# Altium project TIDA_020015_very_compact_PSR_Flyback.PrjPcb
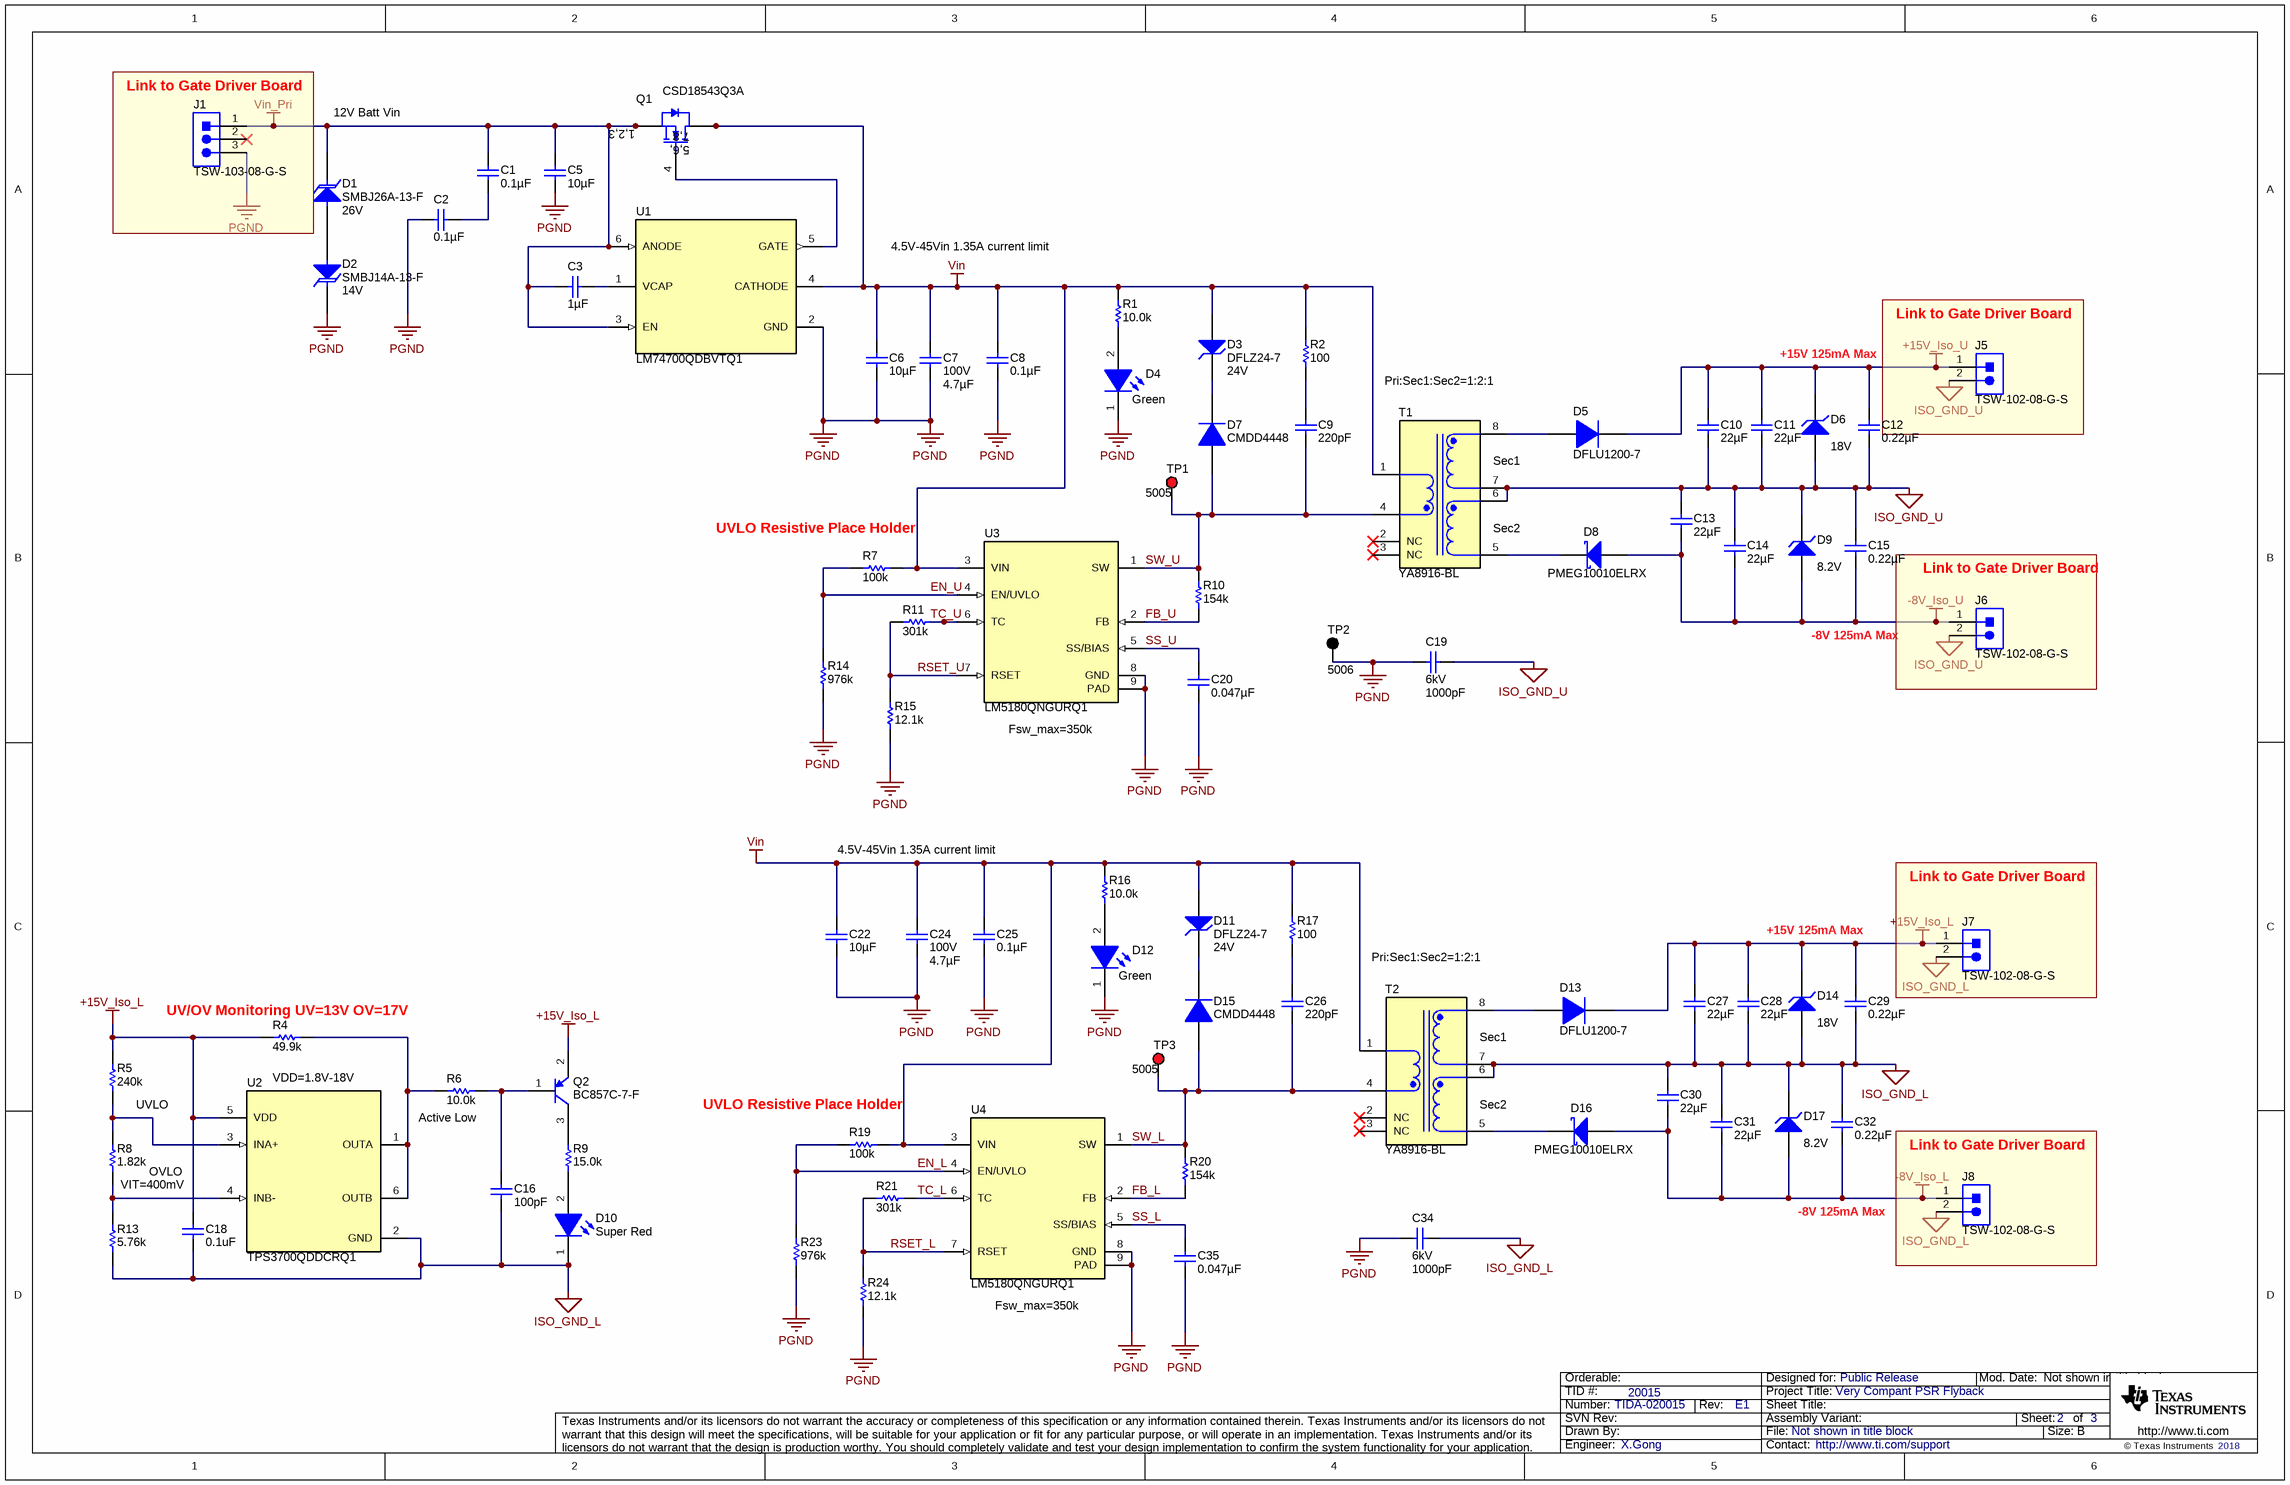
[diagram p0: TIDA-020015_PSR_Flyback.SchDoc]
CopyrightYear: 2018; PCB_Layout: X.Gong; PCB_Rev: E1; PRJ_Customer: Public Release; PRJ_Engineer: X.Gong; PRJ_Number: TIDA-020015; PRJ_Title: Very Compant PSR Flyback; SCH_Rev: E1; TechSupport: http://www.ti.com/support; TID: 20015
2 sheets, 91 parts. Net scope: global (net labels, ports and power ports of the same name join across sheets).
Board file: TIDA_020015_PCB.PcbDoc
Sheets:
  TIDA-020015_PSR_Flyback.SchDoc
  TIDA_020015_PSR_Flyback_Hardware.SchDoc

## Sheet TIDA-020015_PSR_Flyback.SchDoc
size 431 x 279 mm; Date: Not shown in title block; ApprovedBy: Not shown in title block; CheckedBy: Not shown in title block; Author: Not shown in title block; CompanyName: Not shown in title block; Engineer: Not shown in title block; Organization: Not shown in title block; Address1: Not shown in title block; Address2: Not shown in title block; Address3: Not shown in title block; Address4: Not shown in title block; DocumentNumber: 1; Revision: Use project parameter SCH_Rev; SheetNumber: 2; SheetTotal: 3; PageSetup: Record=PageOptions¦CenterHorizontal=True¦CenterVertical=True¦PrintScale=1.00¦XCorrection=1.00¦YCorrection=1.00¦PrintKind=0¦BorderSize=5000000¦LeftOffset=0¦BottomOffset=0¦Orientation=2¦PaperLength=1000¦PaperWidth=1000¦Scale=100¦PaperSource=15¦PrintQuality=600¦MediaType=1¦DitherType=10¦PaperKind=Letter¦PrintScaleMode=1

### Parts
C1  ValueDisplayed: 0.1µF  [0805_HV]  (hidden comment: GRM21BR71H104KA01L)
C2  ValueDisplayed: 0.1µF  [0805_HV]  (hidden comment: GRM21BR71H104KA01L)
C3  ValueDisplayed: 1µF  [0603]  (hidden comment: GRM188R61H105KAALD)
C5  ValueDisplayed: 10µF  [2220_250]  (hidden comment: C5750X7S2A106K230KB)
C6  ValueDisplayed: 10µF  [2220_250]  (hidden comment: C5750X7S2A106K230KB)
C7  VDC_V: 100V  ValueDisplayed: 4.7µF  [1210_220]  (hidden comment: GCM32DC72A475KE02L)
C8  ValueDisplayed: 0.1µF  [0805_HV]  (hidden comment: GRM21BR72A104KAC4L)
C9  ValueDisplayed: 220pF  [0603]  (hidden comment: GRM1885C2A221JA01D)
C10  ValueDisplayed: 22µF  [0805_HV]  (hidden comment: GRM21BR61E226ME44L)
C11  ValueDisplayed: 22µF  [0805_HV]  (hidden comment: GRM21BR61E226ME44L)
C12  ValueDisplayed: 0.22µF  [0805_HV]  (hidden comment: GRM21BR71H224KA01L)
C13  ValueDisplayed: 22µF  [0805_HV]  (hidden comment: GRM21BR61E226ME44L)
C14  ValueDisplayed: 22µF  [0805_HV]  (hidden comment: GRM21BR61E226ME44L)
C15  ValueDisplayed: 0.22µF  [0805_HV]  (hidden comment: GRM21BR71H224KA01L)
C16  ValueDisplayed: 100pF  [0603]  (hidden comment: GRM1885C2A101JA01D)
C18  ValueDisplayed: 0.1uF  [0402]  (hidden comment: Capacitor)
C19  VDC_V: 6kV  ValueDisplayed: 1000pF  [S102_1500x800x1800]  (hidden comment: S102M59Z5UU83L0R)
C20  ValueDisplayed: 0.047µF  [0603]  (hidden comment: GRM188R71C473KA01D)
C22  ValueDisplayed: 10µF  [2220_250]  (hidden comment: C5750X7S2A106K230KB)
C24  VDC_V: 100V  ValueDisplayed: 4.7µF  [1210_220]  (hidden comment: GCM32DC72A475KE02L)
C25  ValueDisplayed: 0.1µF  [0805_HV]  (hidden comment: GRM21BR72A104KAC4L)
C26  ValueDisplayed: 220pF  [0603]  (hidden comment: GRM1885C2A221JA01D)
C27  ValueDisplayed: 22µF  [0805_HV]  (hidden comment: GRM21BR61E226ME44L)
C28  ValueDisplayed: 22µF  [0805_HV]  (hidden comment: GRM21BR61E226ME44L)
C29  ValueDisplayed: 0.22µF  [0805_HV]  (hidden comment: GRM21BR71H224KA01L)
C30  ValueDisplayed: 22µF  [0805_HV]  (hidden comment: GRM21BR61E226ME44L)
C31  ValueDisplayed: 22µF  [0805_HV]  (hidden comment: GRM21BR61E226ME44L)
C32  ValueDisplayed: 0.22µF  [0805_HV]  (hidden comment: GRM21BR71H224KA01L)
C34  VDC_V: 6kV  ValueDisplayed: 1000pF  [S102_1500x800x1800]  (hidden comment: S102M59Z5UU83L0R)
C35  ValueDisplayed: 0.047µF  [0603]  (hidden comment: GRM188R71C473KA01D)
D1  SMBJ26A-13-F  value 26V  [SMB]
D2  SMBJ14A-13-F  value 14V  [SMB]
D3  DFLZ24-7  value 24V  [PowerDI123]
D4  value Green  [WL-SMCW_GREEN]  (hidden comment: 150060GS75000)
D5  DFLU1200-7  [PowerDI123]
D6  value 18V  [SOD-123]  (hidden comment: BZT52C18-7-F)
D7  CMDD4448  [SOD-323]
D8  PMEG10010ELRX  [SOD-123W]
D9  value 8.2V  [SOD-123]  (hidden comment: BZT52C8V2-7-F)
D10  value Super Red  [WL-SMCW_RED]  (hidden comment: 150060SS75000)
D11  DFLZ24-7  value 24V  [PowerDI123]
D12  value Green  [WL-SMCW_GREEN]  (hidden comment: 150060GS75000)
D13  DFLU1200-7  [PowerDI123]
D14  value 18V  [SOD-123]  (hidden comment: BZT52C18-7-F)
D15  CMDD4448  [SOD-323]
D16  PMEG10010ELRX  [SOD-123W]
D17  value 8.2V  [SOD-123]  (hidden comment: BZT52C8V2-7-F)
J1  TSW-103-08-G-S  [Samtec_TSW-103-08-x-S]
J5  TSW-102-08-G-S  [Samtec_TSW-102-08-x-S]
J6  TSW-102-08-G-S  [Samtec_TSW-102-08-x-S]
J7  TSW-102-08-G-S  [Samtec_TSW-102-08-x-S]
J8  TSW-102-08-G-S  [Samtec_TSW-102-08-x-S]
Q1  CSD18543Q3A  [DNH0008A]
Q2  BC857C-7-F  [SOT-23]
R1  ValueDisplayed: 10.0k  [0603]  (hidden comment: CRCW060310K0FKEA)
R2  ValueDisplayed: 100  [0805_HV]  (hidden comment: CRCW0805100RFKEA)
R4  ValueDisplayed: 49.9k  [0402]  (hidden comment: CRCW040249K9FKED)
R5  ValueDisplayed: 240k  [0402]  (hidden comment: CRCW0402240KFKED)
R6  ValueDisplayed: 10.0k  [0402]  (hidden comment: CRCW040210K0FKED)
R7  ValueDisplayed: 100k  [0805_HV]  (hidden comment: CRCW0805100KFKEA)
R8  ValueDisplayed: 1.82k  [0402]  (hidden comment: CRCW04021K82FKED)
R9  ValueDisplayed: 15.0k  [0603]  (hidden comment: CRCW060315K0FKEA)
R10  ValueDisplayed: 154k  [0603]  (hidden comment: CRCW0603154KFKEA)
R11  ValueDisplayed: 301k  [0603]  (hidden comment: CRCW0603301KFKEA)
R13  ValueDisplayed: 5.76k  [0402]  (hidden comment: CRCW04025K76FKED)
R14  ValueDisplayed: 976k  [0603]  (hidden comment: CRCW0603976KFKEA)
R15  ValueDisplayed: 12.1k  [0805_HV]  (hidden comment: CRCW080512K1FKEA)
R16  ValueDisplayed: 10.0k  [0603]  (hidden comment: CRCW060310K0FKEA)
R17  ValueDisplayed: 100  [0805_HV]  (hidden comment: CRCW0805100RFKEA)
R19  ValueDisplayed: 100k  [0805_HV]  (hidden comment: CRCW0805100KFKEA)
R20  ValueDisplayed: 154k  [0603]  (hidden comment: CRCW0603154KFKEA)
R21  ValueDisplayed: 301k  [0603]  (hidden comment: CRCW0603301KFKEA)
R23  ValueDisplayed: 976k  [0603]  (hidden comment: CRCW0603976KFKEA)
R24  ValueDisplayed: 12.1k  [0805_HV]  (hidden comment: CRCW080512K1FKEA)
T1  YA8916-BL  [Coilcraft_YA8916-BL]
T2  YA8916-BL  [Coilcraft_YA8916-BL]
TP1  5005  [Keystone5005]
TP2  5006  [Keystone5006]
TP3  5005  [Keystone5005]
U1  LM74700QDBVTQ1  [DBV0006A_N]
U2  TPS3700QDDCRQ1  [DDC0006A_N]
U3  LM5180QNGURQ1  [NGU0008C]
U4  LM5180QNGURQ1  [NGU0008C]

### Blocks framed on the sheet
Link to Gate Driver Board: J1
Link to Gate Driver Board: J5
Link to Gate Driver Board: J6
Link to Gate Driver Board: J7
Link to Gate Driver Board: J8

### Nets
+15V_Iso_L: C18.1 C27.1 C28.1 C29.1 D13.1(K) D14.1(K) J7.1 Q2.2(E) R4.1 R5.2 U2.5(VDD)
+15V_Iso_U: C10.1 C11.1 C12.1 D5.1(K) D6.1(K) J5.1
-8V_Iso_L: C30.2 C31.2 C32.2 D16.2(A) D17.2(A) J8.1
-8V_Iso_U: C13.2 C14.2 C15.2 D8.2(A) D9.2(A) J6.1
ISO_GND_L: C16.2 C18.2 C27.2 C28.2 C29.2 C30.1 C31.1 C32.1 C34.1 D10.1(K) D14.2(A) D17.1(K) J7.2 J8.2 R13.1 T2.6 T2.7 U2.2(GND)
ISO_GND_U: C10.2 C11.2 C12.2 C13.1 C14.1 C15.1 C19.1 D6.2(A) D9.1(K) J5.2 J6.2 T1.6 T1.7
PGND: C2.1 C5.2 C6.2 C7.2 C8.2 C19.2 C20.2 C22.2 C24.2 C25.2 C34.2 C35.2 D2.1(K) D4.1(K) D12.1(K) J1.3 R14.1 R15.1 R23.1 R24.1 TP2.1 U1.2(GND) U3.8(GND) U3.9(PAD) U4.8(GND) U4.9(PAD)
Vin: C6.1 C7.1 C8.1 C22.1 C24.1 C25.1 D3.2(A) D11.2(A) Q1.5(D) Q1.6(D) Q1.7(D) Q1.8(D) Q1.9(D) R1.2 R2.2 R7.2 R16.2 R17.2 R19.2 T1.1 T2.1 U1.4(CATHODE) U3.3(VIN) U4.3(VIN)
Vin_Pri: C1.1 C3.2 C5.1 D1.1(K) J1.1 Q1.1(S) Q1.2(S) Q1.3(S) U1.3(EN) U1.6(ANODE)
EN_L: R19.1 R23.2 U4.4(EN/UVLO)
EN_U: R7.1 R14.2 U3.4(EN/UVLO)
FB_L: R20.1 U4.2(FB)
FB_U: R10.1 U3.2(FB)
RSET_L: R21.2 R24.2 U4.7(RSET)
RSET_U: R11.2 R15.2 U3.7(RSET)
SS_L: C35.1 U4.5(SS/BIAS)
SS_U: C20.1 U3.5(SS/BIAS)
SW_L: C26.2 D15.2(A) R20.2 T2.4 TP3.1 U4.1(SW)
SW_U: C9.2 D7.2(A) R10.2 T1.4 TP1.1 U3.1(SW)
TC_L: R21.1 U4.6(TC)
TC_U: R11.1 U3.6(TC)
NetC1_2: C1.2 C2.2
NetC3_1: C3.1 U1.1(VCAP)
NetC9_1: C9.1 R2.1
NetC16_1: C16.1 Q2.1(B) R6.2
NetC26_1: C26.1 R17.1
NetD1_2: D1.2(A) D2.2(A)
NetD3_1: D3.1(K) D7.1(K)
NetD4_2: D4.2(A) R1.1
NetD5_2: D5.2(A) T1.8
NetD8_1: D8.1(K) T1.5
NetD10_2: D10.2(A) R9.1
NetD11_1: D11.1(K) D15.1(K)
NetD12_2: D12.2(A) R16.1
NetD13_2: D13.2(A) T2.8
NetD16_1: D16.1(K) T2.5
NetQ1_4: Q1.4(G) U1.5(GATE)
NetQ2_3: Q2.3(C) R9.2
NetR4_2: R4.2 R6.1 U2.1(OUTA) U2.6(OUTB)
NetR5_1: R5.1 R8.2 U2.3(INA+)
NetR8_1: R8.1 R13.2 U2.4(INB-)

Not connected (* = marked no-connect by the designer): J1 2*; T1 2(NC)* 3(NC)*; T2 2(NC)* 3(NC)*

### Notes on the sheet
- 12V Batt Vin
- 4.5V-45Vin 1.35A current limit
- +15V 125mA Max
- (near T1) Pri:Sec1:Sec2=1:2:1
- (near T1) Sec1
- (near R7) UVLO Resistive Place Holder
- (near T1) Sec2
- -8V 125mA Max
- (near U3) Fsw_max=350k
- (near T2) Pri:Sec1:Sec2=1:2:1
- (near R4) UV/OV Monitoring UV=13V OV=17V
- (near T2) Sec1
- UVLO
- VDD=1.8V-18V
- (near R19) UVLO Resistive Place Holder
- (near T2) Sec2
- OVLO
- (near R6) Active Low
- (near R8) VIT=400mV
- (near U4) Fsw_max=350k

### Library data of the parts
C1 C2 = GRM21BR71H104KA01L: CAP, CERM, 0.1 µF, 50 V,+/- 10%, X7R, 0805; Manufacturer: MuRata; Polarized: N; CompType: Capacitor; Value: 0.1uF; U/M: EA; Cap_F: 0.0000001; Tolerance_%: 10; VDC_V: 50; Value2: 50V; TaMin_C: -55; TaMax_C: 125; Cap_Case: 0805; SizeArea_mm2: 2.5; SizeAreaWB_mm2: 6.75; SizeX_mm: 2; SizeY_mm: 1.25; SizeZ_mm: 1.45; AEC Category: Q200; Green_Lifecycle: Active; Green_REACh: Passed
C3 = GRM188R61H105KAALD: CAP, CERM, 1 µF, 50 V,+/- 10%, X5R, 0603; Manufacturer: MuRata; Polarized: N; CompType: Capacitor; Value: 1uF; U/M: EA; Cap_F: 0.000001; Tolerance_%: 10; VDC_V: 50; Value2: 50V; TaMin_C: -55; TaMax_C: 85; SizeArea_mm2: 1.28; SizeAreaWB_mm2: 4.68; SizeX_mm: 1.6; SizeY_mm: 0.8; SizeZ_mm: 1; AEC Category: Q200; Green_Lifecycle: Active; Green_REACh: Passed
C5 C6 C22 = C5750X7S2A106K230KB: CAP, CERM, 10 µF, 100 V,+/- 10%, X7S, 2220; Manufacturer: TDK; Polarized: N; CompType: Capacitor; Value: 10uF; U/M: EA; Cap_F: 0.00001; Tolerance_%: 10; ESR_ohm: 0.003179; Value1: 0.003179 ohm; VDC_V: 100; Value2: 100V; IRMS_A: 5.11992; TaMin_C: -55; TaMax_C: 125; Cap_Case: 2220; SizeArea_mm2: 28.5; SizeAreaWB_mm2: 53.9; SizeX_mm: 5.7; SizeY_mm: 5; SizeZ_mm: 2.5; AEC Category: Q200
C7 C24 = CMP-0082268-1: CAP, CERM, 4.7 µF, 100 V,+/- 10%, X7S, AEC-Q200 Grade 1, 1210; Manufacturer: MuRata; TaMin_C: -55°C; ESR_ohm: 1m; Polarized: N; SizeAreaWB_mm2: 14.7; Value1: 0.001 ohm; U/M: EA; Value: 4.7uF; TaMax_C: 125°C; SizeZ_mm: 2.2; SizeX_mm: 3.2; SizeY_mm: 2.5; Cap_Case: 1210; SizeArea_mm2: 8; AEC Qualified: Y; IRMS_A: 6A; AEC Grade: 1; AEC Category: Q200
C8 C25 = GRM21BR72A104KAC4L: CAP, CERM, 0.1 µF, 100 V,+/- 10%, X7R, 0805; Manufacturer: MuRata; Polarized: N; CompType: Capacitor; Value: 0.1uF; U/M: EA; Cap_F: 0.0000001; Tolerance_%: 10; VDC_V: 100; Value2: 100V; TaMin_C: -55; TaMax_C: 125; Cap_Case: 0805; SizeArea_mm2: 2.5; SizeAreaWB_mm2: 6.75; SizeX_mm: 2; SizeY_mm: 1.25; SizeZ_mm: 1.45; AEC Category: Q200
C9 C26 = GRM1885C2A221JA01D: CAP, CERM, 220 pF, 100 V,+/- 5%, C0G/NP0, 0603; Manufacturer: MuRata; Polarized: N; CompType: Capacitor; Value: 220pF; U/M: EA; Cap_F: 0.00000000022; Tolerance_%: 5; VDC_V: 100; Value2: 100V; TaMin_C: -55; TaMax_C: 125; SizeArea_mm2: 1.28; SizeAreaWB_mm2: 4.68; SizeX_mm: 1.6; SizeY_mm: 0.8; SizeZ_mm: 1; AEC Category: Q200
C10 C11 C13 C14 C27 C28 C30 C31 = GRM21BR61E226ME44L: CAP, CERM, 22 µF, 25 V,+/- 20%, X5R, 0805; Manufacturer: MuRata; Polarized: N; CompType: Capacitor; Value: 22uF; U/M: EA; Cap_F: 0.000022; Tolerance_%: 20; VDC_V: 25; Value2: 25V; TaMin_C: -55; TaMax_C: 85; Cap_Case: 0805; SizeArea_mm2: 2.5; SizeAreaWB_mm2: 6.75; SizeX_mm: 2; SizeY_mm: 1.25; SizeZ_mm: 1.45; AEC Category: Q200; Green_Lifecycle: Active; Green_REACh: Passed
C12 C15 C29 C32 = GRM21BR71H224KA01L: CAP, CERM, 0.22 µF, 50 V,+/- 10%, X7R, 0805; Manufacturer: MuRata; Polarized: N; CompType: Capacitor; Value: 0.22uF; U/M: EA; Cap_F: 0.00000022; Tolerance_%: 10; VDC_V: 50; Value2: 50V; TaMin_C: -55; TaMax_C: 125; Cap_Case: 0805; SizeArea_mm2: 2.5; SizeAreaWB_mm2: 6.75; SizeX_mm: 2; SizeY_mm: 1.25; SizeZ_mm: 1.45; AEC Category: Q200; Green_Lifecycle: Active; Green_REACh: Passed
C16 = GRM1885C2A101JA01D: CAP, CERM, 100 pF, 100 V,+/- 5%, C0G/NP0, 0603; Manufacturer: MuRata; Polarized: N; CompType: Capacitor; Value: 100pF; U/M: EA; Cap_F: 0.0000000001; Tolerance_%: 5; VDC_V: 100; Value2: 100V; TaMin_C: -55; TaMax_C: 125; SizeArea_mm2: 1.28; SizeAreaWB_mm2: 4.68; SizeX_mm: 1.6; SizeY_mm: 0.8; SizeZ_mm: 1; AEC Category: Q200; Green_Lifecycle: Active; Green_REACh: Passed
C18 = CMP-0006562-2: CAP, CERM, 0.1 uF, 10 V, +/- 10%, X5R, 0402; PartNumber: GRM155R61A104KA01D; Manufacturer: MuRata; Polarized: N; Value: 0.1uF; U/M: EA; Cap_F: 100nF; Value1: Unknown; VDC_V: 10V; TaMin_C: -55°C; TaMax_C: 85°C; SizeArea_mm2: 0.5; SizeAreaWB_mm2: 3; SizeX_mm: 1; SizeZ_mm: 0.6; AEC Category: Q200
C19 C34 = CMP-0084156-1: CAP, CERM, 1000 pF, 6000 V,+/- 20%, Z5U, 15x8mm; Manufacturer: Vishay-Bccomponents; TaMin_C: -30°C; Polarized: N; SizeAreaWB_mm2: 170; U/M: EA; Value: 1000pF; TaMax_C: 85°C; SizeZ_mm: 18; SizeX_mm: 15; SizeY_mm: 8; Cap_Case: 15x8x18; Value2: 6000V; SizeArea_mm2: 120; CompType: Capacitor; Cap_F: 1nF; AEC Category: Q200
C20 C35 = GRM188R71C473KA01D: CAP, CERM, 0.047 µF, 16 V,+/- 10%, X7R, 0603; Manufacturer: MuRata; Polarized: N; CompType: Capacitor; Value: 0.047uF; U/M: EA; Cap_F: 0.000000047; Tolerance_%: 10; VDC_V: 16; Value2: 16V; TaMin_C: -55; TaMax_C: 125; SizeArea_mm2: 1.28; SizeAreaWB_mm2: 4.68; SizeX_mm: 1.6; SizeY_mm: 0.8; SizeZ_mm: 1; AEC Category: Q200; Green_Lifecycle: Active; Green_REACh: Passed
D1 = CMP-0005559-2: Diode, TVS, Uni, 26 V, 42.1 Vc, SMB; Manufacturer: Diodes Inc.; Power_W: 5W; SizeAreaWB_mm2: 44.156; U/M: EA; SizeZ_mm: 2.6; SizeX_mm: 5.6; SizeY_mm: 3.81; SizeArea_mm2: 21.336; AEC Category: Q101
D2 = CMP-0005543-2: Diode, TVS, Uni, 14 V, 23.2 Vc, SMB; Manufacturer: Diodes Inc.; Power_W: 5W; SizeAreaWB_mm2: 44.156; U/M: EA; SizeZ_mm: 2.6; SizeX_mm: 5.6; SizeY_mm: 3.81; SizeArea_mm2: 21.336; AEC Category: Q101
D3 D11 = CMP-0005415-2: Diode, Zener, 24 V, 1 W, PowerDI123; Manufacturer: Diodes Inc.; Power_W: 1W; SizeAreaWB_mm2: 13.066; RJA_CperW: 110; U/M: EA; SizeZ_mm: 0.98; SizeX_mm: 3.7; SizeY_mm: 1.78; SizeArea_mm2: 6.586; AEC Category: Q101
D4 D12 = CMP-0002905-1: LED, Green, SMD; Manufacturer: Wurth Elektronik; Io_A: 20mA; Tjmax_C: 85°C; Value1: W; U/M: EA; Angle: 140; Vf_V: 3.2V; Type: InGaN
D5 D13 = CMP-0077072-1: Diode, Superfast Rectifier, 200 V, 1 A, AEC-Q101, PowerDI123; Manufacturer: Diodes Inc.; SizeAreaWB_mm2: 13.066; Vr_V: 200V; SizeArea_mm2: 6.586; AEC Qualified: Y; TJmax_C: 150°C; AEC Category: Q101; Value: 200V; SizeZ_mm: 0.98; Green_REACh: Incomplete; Io_A: 1A; Vf_V: 9.8dV; SizeY_mm: 1.78; Value2: 0.98V; Green_Lifecycle: Not Set; U/M: EA; SizeX_mm: 3.7
D6 D14 = CMP-0084402-1: Diode, Zener, 18 V, 500 mW, AEC-Q101, SOD-123; Manufacturer: Diodes Inc.; AEC Category: Q101; Value1: 0.5W; SizeArea_mm2: 6.545; AEC Qualified: Y; Green_Lifecycle: Active; Power_W: 500mW; SizeZ_mm: 1.35; Green_REACh: Incomplete; SizeY_mm: 1.7; SizeAreaWB_mm2: 13.095; SizeX_mm: 3.85; RJA_CperW: 338
D7 D15 = CMP-0029019-1: Diode, Ultrafast, 75 V, 0.25 A, SOD-323; Manufacturer: Central Semiconductor; Io_A: 2.5dA; Green_Lifecycle: Not Set; SizeAreaWB_mm2: 8.695; Vr_V: 75V; Green_REACh: Incomplete; Value1: 0.25A; TJmax_C: 175°C; U/M: EA; Value: 75V; SizeZ_mm: 1; SizeX_mm: 2.7; SizeY_mm: 1.35; Vf_V: 1.2V; SizeArea_mm2: 3.645; AEC Category: Q101
D8 D16 = CMP-0028782-1: Diode, Schottky, 100 V, 1 A, AEC-Q101, SOD-123W; Manufacturer: Nexperia; Io_A: 1A; Green_Lifecycle: Not Set; SizeAreaWB_mm2: 12.15; Vr_V: 100V; Green_REACh: Incomplete; TJmax_C: 175°C; U/M: EA; Value: 100V; SizeZ_mm: 1; SizeX_mm: 3.5; SizeY_mm: 1.7; Vf_V: 7.7dV; Value2: 0.77V; SizeArea_mm2: 5.95; AEC Qualified: Y; AEC Category: Q101
D9 D17 = CMP-0005813-1: Diode, Zener, 8.2 V, 500 mW, SOD-123; Manufacturer: Diodes Inc.; Power_W: 500mW; SizeAreaWB_mm2: 13.095; Value1: 0.5W; RJA_CperW: 338; U/M: EA; SizeZ_mm: 1.35; SizeX_mm: 3.85; SizeY_mm: 1.7; SizeArea_mm2: 6.545; AEC Category: Q101
D10 = 150060SS75000: LED, Super Red, SMD; Manufacturer: Wurth Elektronik; Type: AlInGaP; Vf_V: 1.9; Value2: 1.9V; Io_A: 0.02; Value1: W; U/M: EA; Green_Lifecycle: Active; Green_REACh: Passed
J1 = CMP-0079327-1: Header, 2.54mm, 3x1, Gold, TH; Manufacturer: Samtec; Pitch_mm: 2.54; Gender: Male; Cert_UL: Y; Shrouded: N; Row_Count: 1
J5-J8 = CMP-0077643-1: Header, 2.54mm, 2x1, Gold, TH; Manufacturer: Samtec; Pitch_mm: 2.54; Gender: Male; Cert_CSA: Y; Current_A: 5.7A; Voltage_V: 550V; Row_Count: 1
Q1 = CSD18543Q3A: MOSFET, N-CH, 60 V, 35 A, DNH0008A (VSONP-8); Manufacturer: Texas Instruments; Alternate Manufacturer: None; U/M: EA; ChType: N; Value: 60V; VdsMax_V: 60; Value1: 0.012 ohm; Rdson45_ohm: 0.012; Value2: 11.1 nC; QgTyp_nC: 11.1; Vgs_V: 20; IdsMax_A: 35; SizeAreaWB_mm2: 18.49; SizeArea_mm2: 10.89; SizeX_mm: 3.3; SizeZ_mm: 0.9; AEC Category: Q101
Q2 = BC857C-7-F, Diodes Inc.: Transistor, PNP, 45 V, 0.1 A, SOT-23; CompType: BJT; PNP: 1; NPN: 0; Vceo_V: 45; Vcesat1_V: 0.075; Value: 45 V; IcRated_A: 0.1; Value1: 0.1 A; HfeMax: 600; TaMin_C: -65; TaMax_C: 150; U/M: EA; AEC Category: Q101
R1 R16 = CRCW060310K0FKEA: RES, 10.0 k, 1%, 0.1 W, 0603; Manufacturer: Vishay-Dale; CompType: Resistor; Value: 10.0k; Res_ohm: 10000; Value_Code: 10k0; Tolerance_%: 1; Power_W: 0.1; Value2: 0.1W; VDC_V: 75; TempCo: 100 ppm/C; SizeArea_mm2: 1.28; SizeX_mm: 1.6; SizeY_mm: 0.8; EIA_Code: E96; U/M: EA; AEC Category: Q200; Green_Lifecycle: Active; Green_REACh: Passed
R2 R17 = CRCW0805100RFKEA: RES, 100, 1%, 0.125 W, 0805; Manufacturer: Vishay-Dale; CompType: Resistor; Value: 100; Value_Code: 100R; Tolerance_%: 1; Power_W: 0.125; Value2: 0.125W; VDC_V: 150; TempCo: 100 ppm/C; SizeArea_mm2: 2.5; SizeX_mm: 2; SizeY_mm: 1.25; SizeZ_mm: 1.45; EIA_Code: E96; U/M: EA; AEC Category: Q200; Green_Lifecycle: Active; Green_REACh: Passed
R4 = CMP-0026403-1: RES, 49.9 k, 1%, 0.063 W, 0402; Manufacturer: Vishay-Dale; Power_W: 63mW; TempCo: 100 ppm/C; Value_Code: 49k9; U/M: EA; Value: 49.9k; EIA_Code: E96; SizeX_mm: 1; SizeY_mm: 0.5; SizeZ_mm: 0.6; Value2: 0.063W; VDC_V: 50V; AEC Category: Q200
R5 = CRCW0402240KFKED: RES, 240 k, 1%, 0.063 W, 0402; Manufacturer: Vishay-Dale; CompType: Resistor; Value: 240k; Res_ohm: 240000; Tolerance_%: 1; Power_W: 0.063; Value2: 0.063W; VDC_V: 50; TempCo: 100 ppm/C; SizeArea_mm2: 0.5; SizeZ_mm: 0.6; U/M: EA; AEC Category: Q200; Green_Lifecycle: Active; Green_REACh: Passed
R6 = CRCW040210K0FKED: RES, 10.0 k, 1%, 0.063 W, 0402; Manufacturer: Vishay-Dale; CompType: Resistor; Value: 10.0k; Res_ohm: 10000; Value_Code: 10k0; Tolerance_%: 1; Power_W: 0.063; Value2: 0.063W; VDC_V: 50; TempCo: 100 ppm/C; SizeArea_mm2: 0.5; SizeZ_mm: 0.6; EIA_Code: E96; U/M: EA; AEC Category: Q200; Green_Lifecycle: Active; Green_REACh: Passed
R7 R19 = CRCW0805100KFKEA: RES, 100 k, 1%, 0.125 W, 0805; Manufacturer: Vishay-Dale; CompType: Resistor; Value: 100k; Res_ohm: 100000; Tolerance_%: 1; Power_W: 0.125; Value2: 0.125W; VDC_V: 150; TempCo: 100 ppm/C; SizeArea_mm2: 2.5; SizeX_mm: 2; SizeY_mm: 1.25; SizeZ_mm: 1.45; EIA_Code: E96; U/M: EA; AEC Category: Q200; Green_Lifecycle: Active; Green_REACh: Passed
R8 = CRCW04021K82FKED: RES, 1.82 k, 1%, 0.063 W, 0402; Manufacturer: Vishay-Dale; CompType: Resistor; Value: 1.82k; Res_ohm: 1820; Value_Code: 1k82; Tolerance_%: 1; Power_W: 0.063; Value2: 0.063W; VDC_V: 50; TempCo: 100 ppm/C; SizeArea_mm2: 0.5; SizeZ_mm: 0.6; EIA_Code: E96; U/M: EA; AEC Category: Q200; Green_Lifecycle: Active; Green_REACh: Passed
R9 = CRCW060315K0FKEA: RES, 15.0 k, 1%, 0.1 W, 0603; Manufacturer: Vishay-Dale; CompType: Resistor; Value: 15.0k; Res_ohm: 15000; Value_Code: 15k0; Tolerance_%: 1; Power_W: 0.1; Value2: 0.1W; VDC_V: 75; TempCo: 100 ppm/C; SizeArea_mm2: 1.28; SizeX_mm: 1.6; SizeY_mm: 0.8; EIA_Code: E96; U/M: EA; AEC Category: Q200; Green_Lifecycle: Active; Green_REACh: Passed
R10 R20 = CRCW0603154KFKEA: RES, 154 k, 1%, 0.1 W, 0603; Manufacturer: Vishay-Dale; CompType: Resistor; Value: 154k; Res_ohm: 154000; Tolerance_%: 1; Power_W: 0.1; Value2: 0.1W; VDC_V: 75; TempCo: 100 ppm/C; SizeArea_mm2: 1.28; SizeX_mm: 1.6; SizeY_mm: 0.8; EIA_Code: E96; U/M: EA; AEC Category: Q200; Green_Lifecycle: Active; Green_REACh: Passed
R11 R21 = CRCW0603301KFKEA: RES, 301 k, 1%, 0.1 W, 0603; Manufacturer: Vishay-Dale; CompType: Resistor; Value: 301k; Res_ohm: 301000; Tolerance_%: 1; Power_W: 0.1; Value2: 0.1W; VDC_V: 75; TempCo: 100 ppm/C; SizeArea_mm2: 1.28; SizeX_mm: 1.6; SizeY_mm: 0.8; EIA_Code: E96; U/M: EA; AEC Category: Q200; Green_Lifecycle: Active; Green_REACh: Passed
R13 = CRCW04025K76FKED: RES, 5.76 k, 1%, 0.063 W, 0402; Manufacturer: Vishay-Dale; CompType: Resistor; Value: 5.76k; Res_ohm: 5760; Value_Code: 5k76; Tolerance_%: 1; Power_W: 0.063; Value2: 0.063W; VDC_V: 50; TempCo: 100 ppm/C; SizeArea_mm2: 0.5; SizeZ_mm: 0.6; EIA_Code: E96; U/M: EA; AEC Category: Q200
R14 R23 = CRCW0603976KFKEA: RES, 976 k, 1%, 0.1 W, 0603; Manufacturer: Vishay-Dale; CompType: Resistor; Value: 976k; Res_ohm: 976000; Tolerance_%: 1; Power_W: 0.1; Value2: 0.1W; VDC_V: 75; TempCo: 100 ppm/C; SizeArea_mm2: 1.28; SizeX_mm: 1.6; SizeY_mm: 0.8; EIA_Code: E96; U/M: EA; AEC Category: Q200
R15 R24 = CRCW080512K1FKEA: RES, 12.1 k, 1%, 0.125 W, 0805; Manufacturer: Vishay-Dale; CompType: Resistor; Value: 12.1k; Res_ohm: 12100; Value_Code: 12k1; Tolerance_%: 1; Power_W: 0.125; Value2: 0.125W; VDC_V: 150; TempCo: 100 ppm/C; SizeArea_mm2: 2.5; SizeX_mm: 2; SizeY_mm: 1.25; SizeZ_mm: 1.45; EIA_Code: E96; U/M: EA; AEC Category: Q200; Green_Lifecycle: Active; Green_REACh: Passed
T1 T2 = CMP-0083973-1: Transformer, 30 uH, SMT; Manufacturer: Coilcraft; SizeAreaWB_mm2: 137.86; SizeArea_mm2: 94.86; AEC Qualified: N; Ns2toNp: 0.52; Lp: 30; AEC Category: Q200; Value: 30uH; SizeZ_mm: 10.6; Ind_H: 30µH; SizeY_mm: 10.2; Ns1toNp: 1; Rsec2_ohm: 3.92d; Rsec1_ohm: 6.95d; DCR_ohm: 3.6d; SizeX_mm: 9.3
TP1 TP3 = CMP-0055142-1: Test Point, Compact, Red, TH; Manufacturer: Keystone; CNHeader: FALSE; Green_Lifecycle: Active; Green_REACh: Passed; ContactFinish: Silver; CT: TRUE
TP2 = CMP-0055143-1: Test Point, Compact, Black, TH; Manufacturer: Keystone; CNHeader: FALSE; Green_Lifecycle: Active; Green_REACh: Passed; ContactFinish: Silver; CT: TRUE
U1 = CMP-0079180-1: Low Iq Always ON Smart Diode Controller, DBV0006A (SOT-23-6); Alternate PartNumber: LM74700QDBVRQ1; Alternate Manufacturer: Texas Instruments; SizeAreaWB_mm2: 14.82; SizeZ_mm: 1.45; SizeX_mm: 2.8; SizeY_mm: 2.9; SizeArea_mm2: 8.12; CompType: IC; AEC Qualified: Y; AEC Category: Q200
U2 = CMP-0067337-2: Automotive, High-Voltage (18V) Window Comparator with Over- and Undervoltage Detection, DDC0006A (SOT-23-T-6); Manufacturer: Texas Instruments; SizeZ_mm: 0.87; SizeX_mm: 1.65; SizeY_mm: 2.95; SizeArea_mm2: 4.8675; CompType: IC; U/M: EA; SizeAreaWB_mm2: 10.4675
U3 U4 = CMP-0078633-2: 70-V PSR Flyback Converter With 100-V, 1.2-A Power Switch and Ultra-Low IQ, NGU0008C (WSON-8); Alternate PartNumber: LM5180QNGUTQ1; Alternate Manufacturer: Texas Instruments; SizeAreaWB_mm2: 25; SizeZ_mm: 0.8; SizeX_mm: 4; SizeArea_mm2: 16; CompType: IC; AEC Qualified: Y; AEC Category: Q200

## Sheet TIDA_020015_PSR_Flyback_Hardware.SchDoc
size 431 x 279 mm; Date: Not shown in title block; ApprovedBy: Not shown in title block; CheckedBy: Not shown in title block; Author: Not shown in title block; CompanyName: Not shown in title block; Engineer: Not shown in title block; Organization: Not shown in title block; Address1: Not shown in title block; Address2: Not shown in title block; Address3: Not shown in title block; Address4: Not shown in title block; DocumentNumber: 1; Revision: Use project parameter SCH_Rev; SheetNumber: 3; SheetTotal: 3; PageSetup: Record=PageOptions¦CenterHorizontal=True¦CenterVertical=True¦PrintScale=1.00¦XCorrection=1.00¦YCorrection=1.00¦PrintKind=0¦BorderSize=5000000¦LeftOffset=0¦BottomOffset=0¦Orientation=2¦PaperLength=1000¦PaperWidth=1000¦Scale=100¦PaperSource=15¦PrintQuality=600¦MediaType=1¦DitherType=10¦PaperKind=Letter¦PrintScaleMode=1
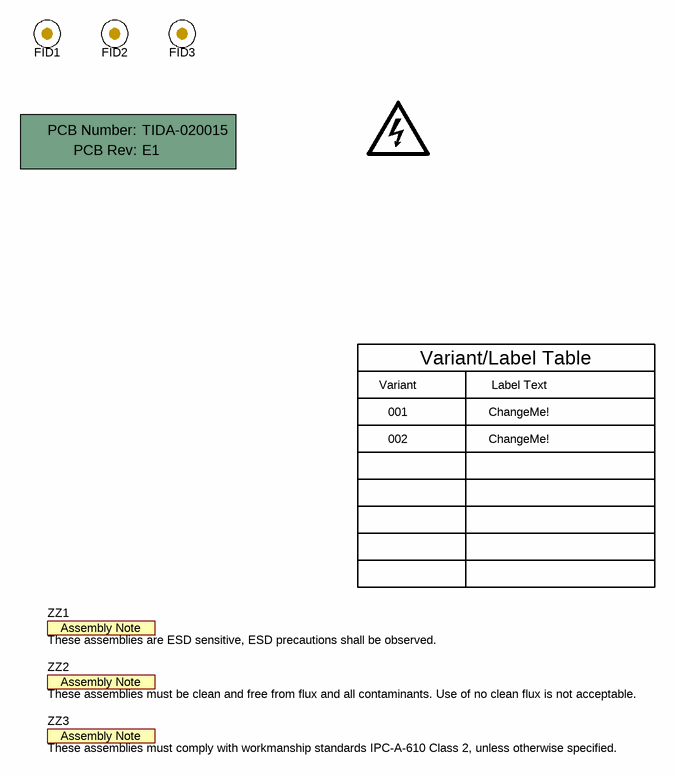
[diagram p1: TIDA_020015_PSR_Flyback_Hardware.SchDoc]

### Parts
!PCB1  Printed Circuit Board  (value not drawn)  (mechanical)
FID1  Fiducial  [Fiducial10-20]  (value not drawn)
FID2  Fiducial  [Fiducial10-20]  (value not drawn)
FID3  Fiducial  [Fiducial10-20]  (value not drawn)
LOGO3  DANGER HIGH VOLTAGE  [IEC_HighVoltage_Small]  (value not drawn)  (no BOM)
ZZ1  These assemblies are ESD sensitive, ESD precautions shall be observed.  [AssemblyNote]  (no BOM)
ZZ2  These assemblies must be clean and free from flux and all contaminants. Use of no clean flux is not acceptable.  [AssemblyNote]  (no BOM)
ZZ3  These assemblies must comply with workmanship standards IPC-A-610 Class 2, unless otherwise specified.  [AssemblyNote]  (no BOM)

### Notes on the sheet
- Variant
- Variant/Label Table
- Label Text
- 001
- 002
- ChangeMe!

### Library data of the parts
!PCB1 = CMP-0003618-2: Manufacturer: Any; PartNumber: TIDA-020015
FID1-FID3 = CMP-0077181-1: Fiducial mark.  There is nothing to buy or mount.
LOGO3 = IEC_HighVoltage: IEC 61010-1 High Voltage Warning; SymbolCreator: a0412235
ZZ1 = CMP-0077236-1
ZZ2 = CMP-0077237-1
ZZ3 = CMP-0077238-1

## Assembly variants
001: not fitted C19 C34 FID1 FID2 FID3 R7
